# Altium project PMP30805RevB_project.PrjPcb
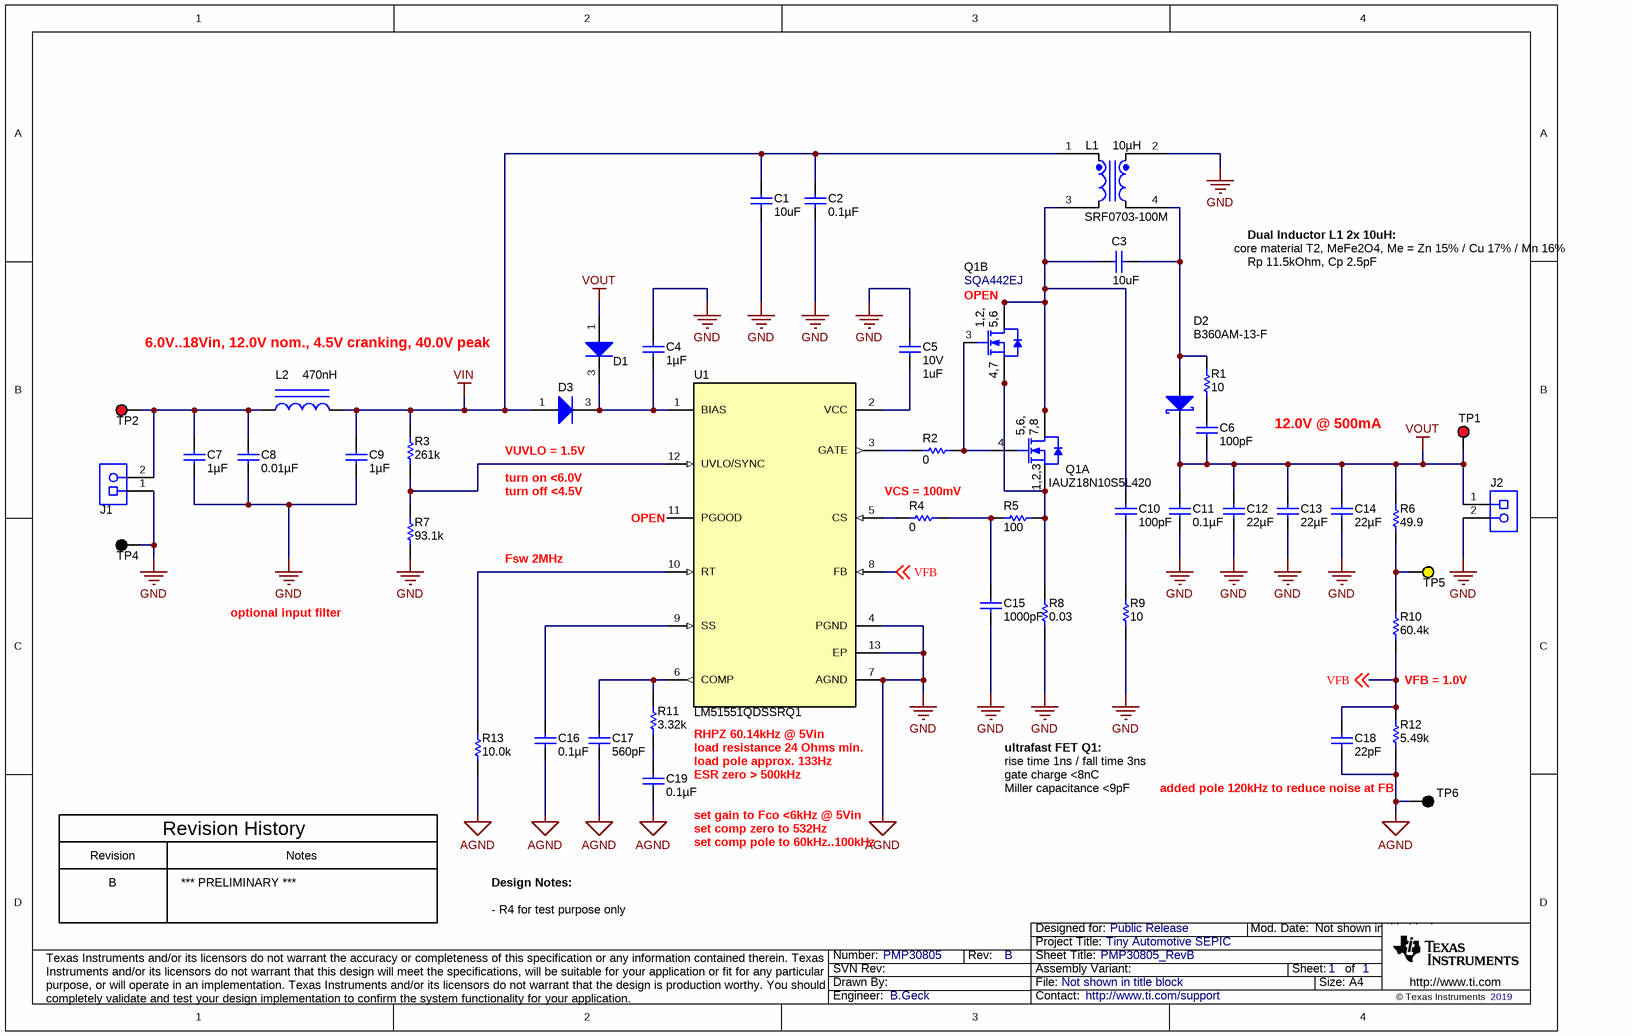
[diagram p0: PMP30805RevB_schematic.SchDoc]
CopyrightYear: 2019; PCB_Layout: B.Geck; PCB_Rev: B; PRJ_Customer: Public Release; PRJ_Engineer: B.Geck; PRJ_Number: PMP30805; PRJ_Title: Tiny Automotive SEPIC; SCH_Rev: B; TechSupport: http://www.ti.com/support; TID: N/A
1 sheet, 47 parts. Net scope: global (net labels, ports and power ports of the same name join across sheets).
Board file: PMP30805RevB_board.PcbDoc

## Sheet PMP30805RevB_schematic.SchDoc: PMP30805_RevB
size A4; Date: Not shown in title block; ApprovedBy: Not shown in title block; CheckedBy: Not shown in title block; Author: Not shown in title block; CompanyName: Not shown in title block; Engineer: Not shown in title block; Organization: Not shown in title block; Address1: Not shown in title block; Address2: Not shown in title block; Address3: Not shown in title block; Address4: Not shown in title block; DocumentNumber: 1; Revision: Use project parameter SCH_Rev; SheetNumber: 1; SheetTotal: 1; PageSetup: Record=PageOptions¦CenterHorizontal=True¦CenterVertical=True¦PrintScale=0.70¦XCorrection=1.00¦YCorrection=1.00¦PrintKind=0¦BorderSize=5000000¦LeftOffset=0¦BottomOffset=0¦Orientation=2¦PaperLength=1000¦PaperWidth=1000¦Scale=100¦PaperSource=15¦PrintQuality=600¦MediaType=1¦DitherType=10¦PaperKind=A4¦PrintScaleMode=1

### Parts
C1  ValueDisplayed: 10uF  [1210_270]  (hidden comment: GRM32ER71H106KA12L)
C2  ValueDisplayed: 0.1µF  [0603]  (hidden comment: GCM188R71H104KA57D)
C3  ValueDisplayed: 10uF  [1210_270]  (hidden comment: GRM32ER71H106KA12L)
C4  Cap_F: 1µF  [0805_HV]  (hidden comment: GRM21BR71H105KA12L)
C5  VDC_V: 10V  ValueDisplayed: 1uF  [0805_HV]  (hidden comment: GRM21BR71A105KA01L)
C6  ValueDisplayed: 100pF  [0603]  (hidden comment: GCM1885C2A101JA16D)
C7  ValueDisplayed: 1µF  [0805_HV]  (hidden comment: GRM21BR71H105KA12L)
C8  ValueDisplayed: 0.01µF  [0603]  (hidden comment: GCM188R71H103KA37D)
C9  ValueDisplayed: 1µF  [0805_HV]  (hidden comment: GRM21BR71H105KA12L)
C10  ValueDisplayed: 100pF  [0603]  (hidden comment: GCM1885C2A101JA16D)
C11  ValueDisplayed: 0.1µF  [0603]  (hidden comment: GRM188R71E104KA01D)
C12  ValueDisplayed: 22µF  [1210_270]  (hidden comment: GRM32ER71E226KE15L)
C13  ValueDisplayed: 22µF  [1210_270]  (hidden comment: GRM32ER71E226KE15L)
C14  ValueDisplayed: 22µF  [1210_270]  (hidden comment: GRM32ER71E226KE15L)
C15  ValueDisplayed: 1000pF  [0603]  (hidden comment: GRM188R71E102KA01D)
C16  ValueDisplayed: 0.1µF  [0603]  (hidden comment: GRM188R71E104KA01D)
C17  ValueDisplayed: 560pF  [0603]  (hidden comment: GRM1885C1E561JA01D)
C18  ValueDisplayed: 22pF  [0603]  (hidden comment: GRM1885C1H220JA01D)
C19  ValueDisplayed: 0.1µF  [0603]  (hidden comment: GRM188R71E104KA01D)
D1  BAS16LT1G  [SOT-23]  (value not drawn)
D2  B360AM-13-F  [SMA]
D3  BAS16LT1G  [SOT-23]  (value not drawn)
J1  ED555/2DS  [TERM_BLK_ED555-2DS]  (value not drawn)
J2  ED555/2DS  [TERM_BLK_ED555-2DS]  (value not drawn)
L1  SRF0703-100M  ValueDisplayed: 10µH  [SRF0703]
L2  ValueDisplayed: 470nH  [SRN4012TA]  (hidden comment: SRN4012TA-R47M)
Q1A  IAUZ18N10S5L420  [PG-TSDSON-8FL]
Q1B  SQA442EJ  [PowerPAK_SC-70]
R1  ValueDisplayed: 10  [0603]  (hidden comment: CRCW060310R0JNEAHP)
R2  ValueDisplayed: 0  [0603]  (hidden comment: ERJ-3GEY0R00V)
R3  ValueDisplayed: 261k  [0603]  (hidden comment: CRCW0603261KFKEA)
R4  ValueDisplayed: 0  [0603]  (hidden comment: ERJ-3GEY0R00V)
R5  ValueDisplayed: 100  [0603]  (hidden comment: CRCW0603100RFKEA)
R6  ValueDisplayed: 49.9  [0603]  (hidden comment: CRCW060349R9FKEA)
R7  ValueDisplayed: 93.1k  [0603]  (hidden comment: CRCW060393K1FKEA)
R8  ValueDisplayed: 0.03  [WSLP0805]  (hidden comment: WSLP0805R0300FEB)
R9  ValueDisplayed: 10  [0603]  (hidden comment: CRCW060310R0JNEAHP)
R10  ValueDisplayed: 60.4k  [0603]  (hidden comment: CRCW060360K4FKEA)
R11  ValueDisplayed: 3.32k  [0603]  (hidden comment: CRCW06033K32FKEA)
R12  ValueDisplayed: 5.49k  [0603]  (hidden comment: CRCW06035K49FKEA)
R13  ValueDisplayed: 10.0k  [0603]  (hidden comment: CRCW060310K0FKEA)
TP1  5010  [Keystone5010]  (value not drawn)
TP2  5010  [Keystone5010]  (value not drawn)
TP4  5011  [Keystone5011]  (value not drawn)
TP5  5014  [Keystone5014]  (value not drawn)
TP6  5011  [Keystone5011]  (value not drawn)
U1  LM51551QDSSRQ1  [DSS0012C]

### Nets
AGND: C1.2 C2.2 C4.1 C5.2 C7.2 C8.2 C9.2 C11.2 C12.2 C13.2 C14.2 C15.2 C16.2 C17.2 C18.2 C19.2 J1.1 J2.2 L1.2 R7.1 R8.1 R9.1 R12.1 R13.1 TP4.1 TP6.1 U1.4(PGND) U1.7(AGND) U1.13(EP)  [also labelled GND]
VIN: C1.1 C2.1 C9.1 D3.1(A) L1.1 L2.2 R3.2
VOUT: C6.2 C11.1 C12.1 C13.1 C14.1 D1.1(A) D2.1(K) J2.1 R6.2 TP1.1
VFB: C18.1 R10.1 R12.2 U1.8(FB) ; off-sheet VFB
NetC3_1: C3.1 D2.2(A) L1.4 R1.2
NetC3_2: C3.2 C10.1 L1.3 Q1A.5(D) Q1A.6(D) Q1A.7(D) Q1A.8(D) Q1A.9(D) Q1B.1(D) Q1B.2(D) Q1B.5(D) Q1B.6(D)
NetC4_2: C4.2 D1.3(K) D3.3(K) U1.1(BIAS)
NetC5_1: C5.1 U1.2(VCC)
NetC6_1: C6.1 R1.1
NetC7_1: C7.1 C8.1 J1.2 L2.1 TP2.1
NetC10_2: C10.2 R9.2
NetC15_1: C15.1 R4.2 R5.1
NetC16_1: C16.1 U1.9(SS)
NetC17_1: C17.1 R11.2 U1.6(COMP)
NetC19_1: C19.1 R11.1
NetQ1A_1: Q1A.1(S) Q1A.2(S) Q1A.3(S) Q1B.4(S) Q1B.7(S) R5.2 R8.2
NetQ1A_4: Q1A.4(G) Q1B.3(G) R2.2
NetR2_1: R2.1 U1.3(GATE)
NetR3_1: R3.1 R7.2 U1.12(UVLO/SYNC)
NetR4_1: R4.1 U1.5(CS)
NetR6_1: R6.1 R10.2 TP5.1
NetR13_2: R13.2 U1.10(RT)

Not connected (* = marked no-connect by the designer): U1 11(PGOOD)

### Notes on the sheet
- core material T2, MeFe2O4, Me = Zn 15% / Cu 17% / Mn 16%
- Dual Inductor L1 2x 10uH:
- (near Q1B) OPEN
- Rp 11.5kOhm, Cp 2.5pF
- 6.0V..18Vin, 12.0V nom., 4.5V cranking, 40.0V peak
- (near D3) VUVLO = 1.5V
- 12.0V @ 500mA
- turn on <6.0V
- turn off <4.5V
- (near U1) OPEN
- VCS = 100mV
- Fsw 2MHz
- optional input filter
- VFB = 1.0V
- RHPZ 60.14kHz @ 5Vin
- load resistance 24 Ohms min.
- load pole approx. 133Hz
- ESR zero > 500kHz
- ultrafast FET Q1:
- rise time 1ns / fall time 3ns
- gate charge <8nC
- Miller capacitance <9pF
- added pole 120kHz to reduce noise at FB
- Revision
- Revision History
- Notes
- (near C19) set gain to Fco <6kHz @ 5Vin
- (near C19) set comp zero to 532Hz
- set comp pole to 60kHz..100kHz
- B
- *** PRELIMINARY ***
- Design Notes:
- - R4 for test purpose only

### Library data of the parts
C1 C3 = CMP-0009226-3: CAP, CERM, 10 uF, 50 V, +/- 10%, X7R, 1210; Manufacturer: MuRata; TaMin_C: -55°C; Polarized: N; SizeAreaWB_mm2: 14.7; Value1: Unknown; U/M: EA; Value: 10uF; TaMax_C: 125°C; SizeZ_mm: 2.7; SizeX_mm: 3.2; SizeY_mm: 2.5; Cap_Case: 1210; Value2: 50V; SizeArea_mm2: 8; Cap_F: 10µF; AEC Category: Q200
C2 = GCM188R71H104KA57D: CAP, CERM, 0.1 µF, 50 V,+/- 10%, X7R, 0603; Manufacturer: MuRata; Polarized: N; CompType: Capacitor; Value: 0.1uF; U/M: EA; Cap_F: 0.0000001; Tolerance_%: 10; ESR_ohm: 0.02; Value1: 0.02 ohm; VDC_V: 50; Value2: 50V; IRMS_A: 1.84; TaMin_C: -55; TaMax_C: 125; SizeArea_mm2: 1.28; SizeAreaWB_mm2: 4.68; SizeX_mm: 1.6; SizeY_mm: 0.8; SizeZ_mm: 1; AEC Category: Q200; Green_Lifecycle: Active; Green_REACh: Passed
C4 = CMP-0008350-2: CAP, CERM, 1 uF, 50 V, +/- 10%, X7R, 0805; Manufacturer: MuRata; TaMin_C: -55°C; Polarized: N; SizeAreaWB_mm2: 6.75; Value1: Unknown; U/M: EA; Value: 1uF; TaMax_C: 125°C; SizeZ_mm: 1.45; SizeX_mm: 2; SizeY_mm: 1.25; Cap_Case: 0805; Value2: 50V; SizeArea_mm2: 2.5; AEC Category: Q200
C5 = CMP-0008313-2: CAP, CERM, 1 uF, 10 V, +/- 10%, X7R, 0805; Manufacturer: MuRata; TaMin_C: -55°C; ESR_ohm: 7m; Polarized: N; SizeAreaWB_mm2: 6.75; Value1: 0.007 ohm; U/M: EA; Value: 1uF; TaMax_C: 125°C; SizeZ_mm: 1.45; SizeX_mm: 2; SizeY_mm: 1.25; Cap_Case: 0805; SizeArea_mm2: 2.5; Cap_F: 1µF; AEC Category: Q200
C6 C10 = GCM1885C2A101JA16D: CAP, CERM, 100 pF, 100 V,+/- 5%, C0G/NP0, AEC-Q200 Grade 1, 0603; Manufacturer: MuRata; Polarized: N; CompType: Capacitor; Value: 100pF; U/M: EA; Cap_F: 0.0000000001; Tolerance_%: 5; VDC_V: 100; Value2: 100V; TaMin_C: -55; TaMax_C: 125; SizeArea_mm2: 1.28; SizeAreaWB_mm2: 4.68; SizeX_mm: 1.6; SizeY_mm: 0.8; SizeZ_mm: 1; AEC Category: Q200; AEC Qualified: Y
C7 C9 = GRM21BR71H105KA12L: CAP, CERM, 1 µF, 50 V,+/- 10%, X7R, 0805; Manufacturer: MuRata; Polarized: N; CompType: Capacitor; Value: 1uF; U/M: EA; Cap_F: 0.000001; Tolerance_%: 10; VDC_V: 50; Value2: 50V; TaMin_C: -55; TaMax_C: 125; Cap_Case: 0805; SizeArea_mm2: 2.5; SizeAreaWB_mm2: 6.75; SizeX_mm: 2; SizeY_mm: 1.25; SizeZ_mm: 1.45; AEC Category: Q200; Green_Lifecycle: Active; Green_REACh: Passed
C8 = GCM188R71H103KA37D: CAP, CERM, 0.01 µF, 50 V,+/- 10%, X7R, AEC-Q200 Grade 1, 0603; Manufacturer: MuRata; Polarized: N; CompType: Capacitor; Value: 0.01uF; U/M: EA; Cap_F: 0.00000001; Tolerance_%: 10; VDC_V: 50; Value2: 50V; TaMin_C: -55; TaMax_C: 125; SizeArea_mm2: 1.28; SizeAreaWB_mm2: 4.68; SizeX_mm: 1.6; SizeY_mm: 0.8; SizeZ_mm: 1; AEC Category: Q200; AEC Qualified: Y
C11 C16 C19 = GRM188R71E104KA01D: CAP, CERM, 0.1 µF, 25 V,+/- 10%, X7R, 0603; Manufacturer: MuRata; Polarized: N; CompType: Capacitor; Value: 0.1uF; U/M: EA; Cap_F: 0.0000001; Tolerance_%: 10; VDC_V: 25; Value2: 25V; TaMin_C: -55; TaMax_C: 125; SizeArea_mm2: 1.28; SizeAreaWB_mm2: 4.68; SizeX_mm: 1.6; SizeY_mm: 0.8; SizeZ_mm: 1; AEC Category: Q200; Green_Lifecycle: Active; Green_REACh: Passed
C12-C14 = GRM32ER71E226KE15L: CAP, CERM, 22 µF, 25 V,+/- 10%, X7R, 1210; Manufacturer: MuRata; Polarized: N; CompType: Capacitor; Value: 22uF; U/M: EA; Cap_F: 0.000022; Tolerance_%: 10; ESR_ohm: 0.002334; Value1: 0.002334 ohm; VDC_V: 25; Value2: 25V; IRMS_A: 3.832999; TaMin_C: -55; TaMax_C: 125; Cap_Case: 1210; SizeArea_mm2: 8; SizeAreaWB_mm2: 14.7; SizeX_mm: 3.2; SizeY_mm: 2.5; SizeZ_mm: 2.7; AEC Category: Q200; Green_Lifecycle: Active; Green_REACh: Passed
C15 = GRM188R71E102KA01D: CAP, CERM, 1000 pF, 25 V,+/- 10%, X7R, 0603; Manufacturer: MuRata; Polarized: N; CompType: Capacitor; Value: 1000pF; U/M: EA; Cap_F: 0.000000001; Tolerance_%: 10; VDC_V: 25; Value2: 25V; TaMin_C: -55; TaMax_C: 125; SizeArea_mm2: 1.28; SizeAreaWB_mm2: 4.68; SizeX_mm: 1.6; SizeY_mm: 0.8; SizeZ_mm: 1; AEC Category: Q200; Green_Lifecycle: Active; Green_REACh: Passed
C17 = GRM1885C1E561JA01D: CAP, CERM, 560 pF, 25 V,+/- 5%, C0G/NP0, 0603; Manufacturer: MuRata; Polarized: N; CompType: Capacitor; Value: 560pF; U/M: EA; Cap_F: 0.00000000056; Tolerance_%: 5; VDC_V: 25; Value2: 25V; TaMin_C: -55; TaMax_C: 125; SizeArea_mm2: 1.28; SizeAreaWB_mm2: 4.68; SizeX_mm: 1.6; SizeY_mm: 0.8; SizeZ_mm: 1; AEC Category: Q200
C18 = GRM1885C1H220JA01D: CAP, CERM, 22 pF, 50 V,+/- 5%, C0G/NP0, 0603; Manufacturer: MuRata; Polarized: N; CompType: Capacitor; Value: 22pF; U/M: EA; Cap_F: 0.000000000022; Tolerance_%: 5; VDC_V: 50; Value2: 50V; TaMin_C: -55; TaMax_C: 125; SizeArea_mm2: 1.28; SizeAreaWB_mm2: 4.68; SizeX_mm: 1.6; SizeY_mm: 0.8; SizeZ_mm: 1; AEC Category: Q200; Green_Lifecycle: Active; Green_REACh: Passed
D1 D3 = CMP-0029193-2: Diode, Switching, 100 V, 0.2 A, SOT-23; Manufacturer: ON Semiconductor; Value: 100V; Green_Lifecycle: Active; SizeAreaWB_mm2: 14; Vf_V: 1.25V; SizeZ_mm: 1.1; AEC Qualified: N; SizeX_mm: 2.5; Green_REACh: Passed; AEC Category: Q101; Value1: 0.2A; SizeY_mm: 3; SizeArea_mm2: 7.5; Io_A: 200mA; TJmax_C: 150°C
D2 = B360AM-13-F: Diode, Schottky, 60 V, 3 A, AEC-Q101, SMA; Manufacturer: Diodes Inc.; U/M: EA; Vf_V: 0.7; Value: 60V; Value1: 3A; Value2: 0.7V; Io_A: 3; Vr_V: 60; TJmax_C: 150; SizeAreaWB_mm2: 37.3428; SizeArea_mm2: 16.3228; SizeX_mm: 5.59; SizeY_mm: 2.92; SizeZ_mm: 2.87; AEC Category: Q101; AEC Qualified: Y; Green_Lifecycle: Not Set; Green_REACh: Incomplete
J1 J2 = CMP-0074913-1: Terminal Block, 3.5mm Pitch, 2x1, TH; Manufacturer: On-Shore Technology; Cert_VDE: Y; CNHeader: False; Current_A: 6A; Green_Lifecycle: Active; Shrouded: N; Gender: Female; Green_REACh: Passed; Voltage_V: 150V; Row_Count: 1; Pitch_mm: 3.5; ContactFinish: Brass; CT: True
L1 = SRF0703-100M: Coupled inductor, 10 µH, 2.47 A, 0.1652 ohm, SMD; Manufacturer: Bourns; SymbolCreator: a0412235; SizeAreaWB_mm2: 92.16; SizeArea_mm2: 57.76; SizeX_mm: 7.6; SizeZ_mm: 3.4; Value: 10uH; Ind_H: 10.0E-6; DCR_ohm: 0.1652; AEC Category: Q200; AEC Qualified: N
L2 = SRN4012TA-R47M: Inductor, Shielded, Ferrite, 470 nH, 3.2 A, 0.03 ohm, AEC-Q200 Grade 1, SMD; Manufacturer: Bourns; Value: 470nH; Ind_H: 470.0E-9; Imax_A: 3.2; Irms: 3.2A @ 40C rise; Isat: 4A @ 30% inductance drop; DCR_ohm: 0.03; Value2: 3.2A; SizeAreaWB_mm2: 25; SizeArea_mm2: 16; SizeX_mm: 4; SizeZ_mm: 1.2; AEC Category: Q200; AEC Qualified: Y; AEC Grade: 1; Green_Lifecycle: Active; Green_REACh: Passed
Q1A = BSZ013NE2LS5IATMA1: MOSFET, N-CH, 100 V, 40 A, 8-PG-TSDSON; Manufacturer: Infineon Technologies; Alternate Manufacturer: None; U/M: EA; ChType: N; Value: 100V; VdsMax_V: 100; Value1: 0.055 ohm; Rdson45_ohm: 0.055; Value2: 5.4 nC; QgTyp_nC: 5.4; Vgs_V: 20; IdsMax_A: 18; SizeAreaWB_mm2: 18.49; SizeArea_mm2: 10.89; SizeX_mm: 3.3; SizeZ_mm: 1.1; AEC Category: Q101; AEC Qualified: Y; Green_Lifecycle: Active; Green_REACh: Passed
Q1B = CMP-0000233-1: MOSFET, N-CH, 60 V, 9 A, AEC-Q101, PowerPAK SC-70; PartNumber: SQA442EJ-T1_GE3; Alternate Manufacturer: None; Manufacturer: Vishay-Siliconix; SizeZ_mm: 0.8; ChType: N; Value2: 9.7 nC; Value1: 0.032; VdsMax_V: 60V; SizeX_mm: 2.05; Vgs_V: 20V; AEC Qualified: Y; Value: 60V; Rdson45_ohm: 28m; SizeArea_mm2: 4.2025; AEC Category: Q101; IdsMax_A: 7.8A; SizeAreaWB_mm2: 9.3025; U/M: EA; QgTyp_nC: 5
R1 R9 = CRCW060310R0JNEAHP: RES, 10, 5%, 0.25 W, 0603; Manufacturer: Vishay-Dale; CompType: Resistor; Value: 10; Value_Code: 10R0; Tolerance_%: 5; Power_W: 0.25; Value2: 0.25W; VDC_V: 75; TempCo: 200 ppm/C; SizeArea_mm2: 1.28; SizeX_mm: 1.6; SizeY_mm: 0.8; SizeZ_mm: 1; EIA_Code: E24; U/M: EA; AEC Category: Q200; Green_Lifecycle: Active; Green_REACh: Passed
R2 R4 = CMP-0025874-4: RES, 0, 5%, 0.1 W, AEC-Q200 Grade 0, 0603; Manufacturer: Panasonic; Power_W: 100mW; TempCo: 600 ppm/C; Value_Code: 0000; Value: 0; EIA_Code: E24; SizeX_mm: 1.6; SizeY_mm: 0.8; SizeZ_mm: 1; Value2: 0.1W; SizeArea_mm2: 1.28; AEC Qualified: Y; VDC_V: 50V; AEC Category: Q200; SizeAreaWB_mm2: 4.68
R3 = CMP-0022244-4: RES, 261 k, 1%, 0.1 W, AEC-Q200 Grade 0, 0603; Manufacturer: Vishay-Dale; Power_W: 100mW; TempCo: 100 ppm/C; Value: 261k; EIA_Code: E96; SizeX_mm: 1.6; SizeY_mm: 0.8; SizeZ_mm: 1; Value2: 0.1W; SizeArea_mm2: 1.28; AEC Qualified: Y; VDC_V: 75V; AEC Category: Q200; AEC Grade: 0
R5 = CMP-0021991-2: RES, 100, 1%, 0.1 W, 0603; Manufacturer: Vishay-Dale; Power_W: 100mW; TempCo: 100 ppm/C; Value_Code: 100R; U/M: EA; Value: 100; EIA_Code: E96; SizeX_mm: 1.6; SizeY_mm: 0.8; SizeZ_mm: 1; Value2: 0.1W; SizeArea_mm2: 1.28; VDC_V: 75V; AEC Category: Q200
R6 = CMP-0022448-4: RES, 49.9, 1%, 0.1 W, AEC-Q200 Grade 0, 0603; Manufacturer: Vishay-Dale; Power_W: 100mW; TempCo: 100 ppm/C; Value_Code: 49R9; Value: 49.9; EIA_Code: E96; SizeX_mm: 1.6; SizeY_mm: 0.8; SizeZ_mm: 1; Value2: 0.1W; SizeArea_mm2: 1.28; AEC Qualified: Y; VDC_V: 75V; AEC Category: Q200; AEC Grade: 0
R7 = CMP-0022655-4: RES, 93.1 k, 1%, 0.1 W, AEC-Q200 Grade 0, 0603; Manufacturer: Vishay-Dale; Power_W: 100mW; TempCo: 100 ppm/C; Value_Code: 93k1; Value: 93.1k; EIA_Code: E96; SizeX_mm: 1.6; SizeY_mm: 0.8; SizeZ_mm: 1; Value2: 0.1W; SizeArea_mm2: 1.28; AEC Qualified: Y; VDC_V: 75V; AEC Category: Q200; AEC Grade: 0
R8 = WSLP0805R0300FEB: RES, 0.03, 1%, 0.5 W, 0805; Manufacturer: Vishay-Dale; CompType: Resistor; Value: 0.03; Value_Code: R030; Tolerance_%: 1; Power_W: 0.5; Value2: 0.5W; TempCo: 75 ppm/C; SizeArea_mm2: 2.5781; SizeX_mm: 2.03; SizeY_mm: 1.27; SizeZ_mm: 0.635; EIA_Code: E96; U/M: EA; AEC Category: Q200; AEC Qualified: N
R10 = CMP-0022532-4: RES, 60.4 k, 1%, 0.1 W, AEC-Q200 Grade 0, 0603; Manufacturer: Vishay-Dale; Power_W: 100mW; TempCo: 100 ppm/C; Value_Code: 60k4; Value: 60.4k; EIA_Code: E96; SizeX_mm: 1.6; SizeY_mm: 0.8; SizeZ_mm: 1; Value2: 0.1W; SizeArea_mm2: 1.28; AEC Qualified: Y; VDC_V: 75V; AEC Category: Q200; AEC Grade: 0
R11 = CRCW06033K32FKEA: RES, 3.32 k, 1%, 0.1 W, 0603; Manufacturer: Vishay-Dale; CompType: Resistor; Value: 3.32k; Res_ohm: 3320; Value_Code: 3k32; Tolerance_%: 1; Power_W: 0.1; Value2: 0.1W; VDC_V: 75; TempCo: 100 ppm/C; SizeArea_mm2: 1.28; SizeX_mm: 1.6; SizeY_mm: 0.8; EIA_Code: E96; U/M: EA; AEC Category: Q200; Green_Lifecycle: Active; Green_REACh: Passed
R12 = CMP-0022512-4: RES, 5.49 k, 1%, 0.1 W, AEC-Q200 Grade 0, 0603; Manufacturer: Vishay-Dale; Power_W: 100mW; TempCo: 100 ppm/C; Value_Code: 5k49; Value: 5.49k; EIA_Code: E96; SizeX_mm: 1.6; SizeY_mm: 0.8; SizeZ_mm: 1; Value2: 0.1W; SizeArea_mm2: 1.28; AEC Qualified: Y; VDC_V: 75V; AEC Category: Q200; AEC Grade: 0
R13 = CRCW060310K0FKEA: RES, 10.0 k, 1%, 0.1 W, 0603; Manufacturer: Vishay-Dale; CompType: Resistor; Value: 10.0k; Res_ohm: 10000; Value_Code: 10k0; Tolerance_%: 1; Power_W: 0.1; Value2: 0.1W; VDC_V: 75; TempCo: 100 ppm/C; SizeArea_mm2: 1.28; SizeX_mm: 1.6; SizeY_mm: 0.8; EIA_Code: E96; U/M: EA; AEC Category: Q200; Green_Lifecycle: Active; Green_REACh: Passed
TP1 TP2 = CMP-0055147-1: Test Point, Multipurpose, Red, TH; Manufacturer: Keystone; CNHeader: FALSE; Green_Lifecycle: Active; Green_REACh: Passed; ContactFinish: Silver; CT: TRUE
TP4 TP6 = CMP-0055148-1: Test Point, Multipurpose, Black, TH; Manufacturer: Keystone; CNHeader: FALSE; Green_Lifecycle: Active; Green_REACh: Passed; ContactFinish: Silver; CT: TRUE
TP5 = CMP-0055151-1: Test Point, Multipurpose, Yellow, TH; Manufacturer: Keystone; CNHeader: FALSE; Green_Lifecycle: Active; Green_REACh: Passed; ContactFinish: Silver; CT: TRUE
U1 = CMP-0081541-1: Automotive Grade 2.2-MHz Wide Input Non-synchronous Boost Controller, DSS0012C (WSON-12); Alternate PartNumber: LM51551QDSSTQ1; Alternate Manufacturer: Texas Instruments; SizeAreaWB_mm2: 12; SizeZ_mm: 0.8; SizeX_mm: 2; SizeY_mm: 3; SizeArea_mm2: 6; CompType: IC; AEC Qualified: Y; AEC Category: Q200

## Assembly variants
Q1A: not fitted Q1B
Q1B: not fitted Q1A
